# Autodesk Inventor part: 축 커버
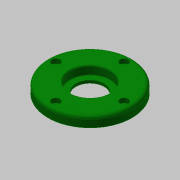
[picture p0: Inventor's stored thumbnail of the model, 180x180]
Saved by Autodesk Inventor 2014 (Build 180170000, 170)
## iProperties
Created: 2015-10
Part Number: 축 커버
Document SubType Name: Modeling
Designer: mdu
Density: 1 g/cm^3
Material: 일반
Appearance: Dark Green
Author: mdu
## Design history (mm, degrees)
sketch "스케치1"
  geometry: C1 r 40 at (0, 0) reference; C2 r 26 at (0, 0) reference; 1 further point
  node "참조1"
  node "참조2"
extrude "돌출1" new body sketch "스케치1" distance "d0" = 10; taper "d1" = 0 deg
extrude "돌출2" join sketch "스케치1" distance "d2" = 4; taper "d3" = 0 deg
hole "구멍1" diameter "d6" = 27; stored, may be unused: countersink angle "d10" = 90 deg, drill point angle "d12" = 118 deg; dims "d7" = 6, "d8" = 38, "d9" = 8.3, "d11" = 8, "d33" = 10, "d34" = 10
sketch "스케치2"
  geometry: C1 r 20 at (0, 0); 1 further point
  constraints: 1 centre point, 1 coincident
  dimensions: "d13" = 40 diameter of C1
extrude "돌출3" cut sketch "스케치2" distance "d14" = 3; taper "d15" = 0 deg
sketch "스케치3"
  geometry: C1 r 1.621 at (0, 32.5) reference; 1 further point
hole "구멍2" sketch "스케치3" at (0, 32.5) diameter "d16" = 4.5; stored, may be unused: countersink angle "d20" = 90 deg, drill point angle "d22" = 118 deg; dims "d17" = 6, "d18" = 8, "d19" = 4.4, "d21" = 8
fillet "모깎기1" dims "d26" = 3, "d27" = 0.3
chamfer "모따기1" distance "d28" = 1; stored, may be unused: second distance "d29" = 2, angle "d30" = 45 deg
chamfer "모따기2" distance "d31" = 0.8; stored, may be unused: second distance "d32" = 2, angle "d35" = 30 deg
node "솔리드1"
pattern_circular "원형 패턴1" dims angle "d24" = 360 deg
node "참조3"
